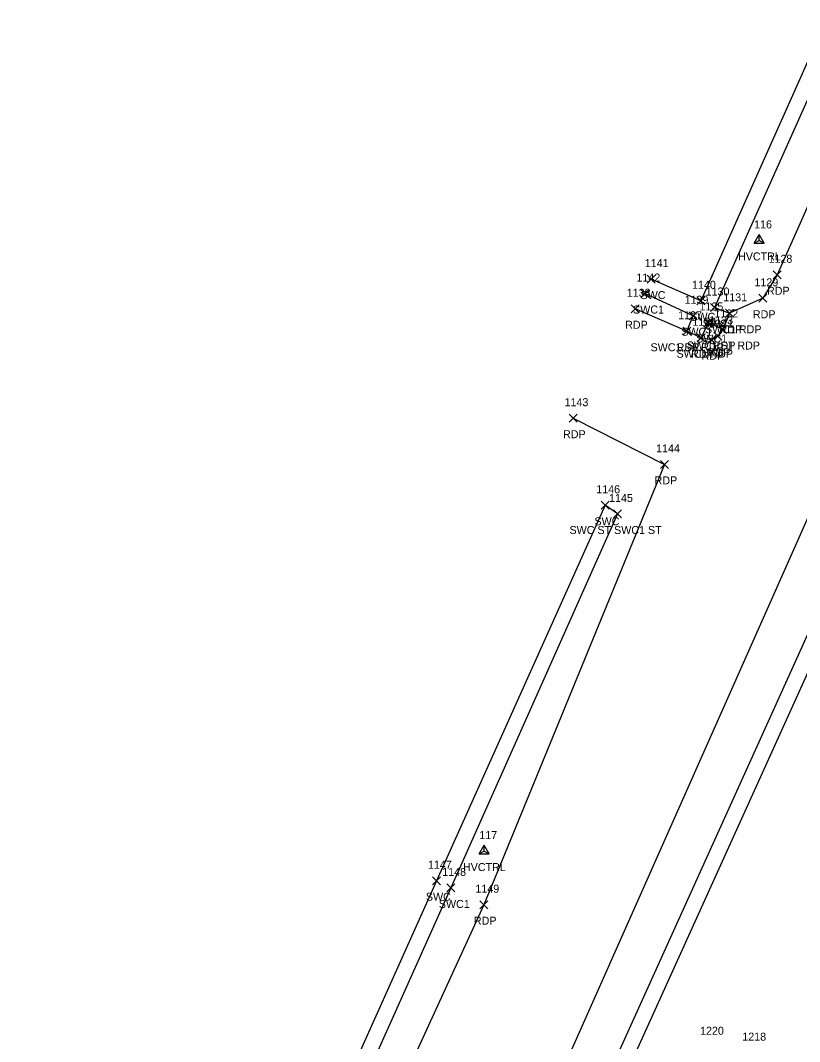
# Model space of a CAD drawing. Extents: x 1767353 to 1772625, y 740790 to 747702.
# Drawn here: x 1769882.6 to 1770077.3, y 742414.3 to 742669.5 of the extents above; entities that cross this region are included whole.
import ezdxf

# ---------------------------------------------------------------- set-up
doc = ezdxf.new("R2010")
doc.units = 0
for name, color, linetype in [('C_A', 7, 'Continuous'), ('C_I', 7, 'Continuous'), ('CPSM', 7, 'Continuous'), ('L_I', 7, 'Continuous'), ('P_A', 7, 'Continuous'), ('P_I', 7, 'Continuous'), ('P_TIC', 7, 'Continuous'), ('PET', 7, 'Continuous'), ('R_A', 7, 'Continuous'), ('R_I', 7, 'Continuous'), ('R_TIC', 7, 'Continuous'), ('RSW', 7, 'Continuous')]:
    doc.layers.add(name, color=color, linetype=linetype)

msp = doc.modelspace()

# ---------------------------------------------------------------- linework, layer by layer
at = {"layer": 'CPSM'}
for p, q in [((1770066.01, 742613.81), (1770067.26, 742615.97)), ((1770068.51, 742613.81), (1770067.26, 742615.97)), ((1770067.26, 742614.53), (1770067.26, 742615.97)), ((1770066.01, 742613.81), (1770067.26, 742614.53)), ((1770066.01, 742613.81), (1770068.51, 742613.81)), ((1770067.26, 742614.53), (1770067.26, 742614.53)), ((1770067.26, 742614.53), (1770068.51, 742613.81)), ((1769997.27, 742461.22), (1769998.52, 742463.38)), ((1769999.77, 742461.22), (1769998.52, 742463.38)), ((1769998.52, 742461.94), (1769998.52, 742463.38)), ((1769997.27, 742461.22), (1769998.52, 742461.94)), ((1769997.27, 742461.22), (1769999.77, 742461.22)), ((1769998.52, 742461.94), (1769998.52, 742461.94)), ((1769998.52, 742461.94), (1769999.77, 742461.22))]:
    msp.add_line(p, q, dxfattribs=at)
at = {"layer": 'P_TIC'}
for points in [[(1770070.7, 742604.94), (1770072.7, 742606.94)], [(1770072.7, 742604.94), (1770070.7, 742606.94)], [(1770067.18, 742599.07), (1770069.18, 742601.07)], [(1770069.18, 742599.07), (1770067.18, 742601.07)], [(1770035.26, 742596.45), (1770037.26, 742598.45)], [(1770037.26, 742596.45), (1770035.26, 742598.45)], [(1770058.84, 742595.32), (1770060.84, 742597.32)], [(1770060.84, 742595.32), (1770058.84, 742597.32)], [(1770048.12, 742590.83), (1770050.12, 742592.83)], [(1770050.12, 742590.83), (1770048.12, 742592.83)], [(1770057.18, 742591.27), (1770059.18, 742593.27)], [(1770059.18, 742591.27), (1770057.18, 742593.27)], [(1770051.72, 742589.21), (1770053.72, 742591.21)], [(1770053.72, 742589.21), (1770051.72, 742591.21)], [(1770054.34, 742588.72), (1770056.34, 742590.72)], [(1770056.34, 742588.72), (1770054.34, 742590.72)], [(1770055.9, 742589.58), (1770057.9, 742591.58)], [(1770057.9, 742589.58), (1770055.9, 742591.58)], [(1770019.73, 742569.11), (1770021.73, 742571.11)], [(1770021.73, 742569.11), (1770019.73, 742571.11)], [(1770042.61, 742557.57), (1770044.61, 742559.57)], [(1770044.61, 742557.57), (1770042.61, 742559.57)], [(1769997.45, 742447.54), (1769999.45, 742449.54)], [(1769999.45, 742447.54), (1769997.45, 742449.54)]]:
    msp.add_lwpolyline(points, dxfattribs=at)
at = {"layer": 'PET'}
for points in [[(1770287.36, 743218.01), (1770265.05, 743131.43), (1770236.51, 743031.56), (1770219.34, 742972.95), (1770201.78, 742917.74), (1770184.32, 742871.03), (1770170.89, 742832.33), (1770155.31, 742796.84), (1770127.15, 742730.43), (1770071.7, 742605.94), (1770068.18, 742600.07), (1770059.84, 742596.32), (1770058.18, 742592.27), (1770056.9, 742590.58), (1770055.34, 742589.72), (1770052.72, 742590.21), (1770049.12, 742591.83), (1770036.26, 742597.45)], [(1770147.48, 742699.94), (1770126.77, 742647.43), (1770093.35, 742575.6), (1770087.72, 742564.06), (1770014.02, 742398.02), (1769942.32, 742243.2), (1769914.15, 742124.85), (1769908.32, 742119.68), (1769902.88, 742101.36), (1769903.35, 742099.19), (1769904.66, 742097.46), (1769909.68, 742095.79), (1770083.39, 742045.68), (1770106.4, 742043.42), (1770086.96, 742009.25), (1770086.23, 742007.27), (1770086.55, 742005.47), (1770087.9, 742003.62), (1770089.26, 742002.56), (1770097.29, 741998.16), (1770140.08, 741981.73)], [(1770020.73, 742570.11), (1770043.61, 742558.57), (1769998.45, 742448.54), (1769947.65, 742337.89), (1769907.74, 742250.04), (1769890.69, 742225.86), (1769843.08, 742118.46), (1769841.73, 742116.98), (1769840.43, 742116.75), (1769837.14, 742117.6), (1769825.35, 742123.03), (1769532.9, 742252.54)]]:
    msp.add_lwpolyline(points, dxfattribs=at)
at = {"layer": 'R_TIC'}
for points in [[(1770039.21, 742603.87), (1770041.21, 742605.87)], [(1770041.21, 742603.87), (1770039.21, 742605.87)], [(1770037.69, 742600.26), (1770039.69, 742602.26)], [(1770039.69, 742600.26), (1770037.69, 742602.26)], [(1770051.67, 742598.45), (1770053.67, 742600.45)], [(1770053.67, 742598.45), (1770051.67, 742600.45)], [(1770055.07, 742596.76), (1770057.07, 742598.76)], [(1770057.07, 742596.76), (1770055.07, 742598.76)], [(1770049.74, 742594.71), (1770051.74, 742596.71)], [(1770051.74, 742594.71), (1770049.74, 742596.71)], [(1770058.84, 742595.32), (1770060.84, 742597.32)], [(1770060.84, 742595.32), (1770058.84, 742597.32)], [(1770048.12, 742590.83), (1770050.12, 742592.83)], [(1770050.12, 742590.83), (1770048.12, 742592.83)], [(1770053.46, 742593.02), (1770055.46, 742595.02)], [(1770055.46, 742593.02), (1770053.46, 742595.02)], [(1770057.18, 742591.27), (1770059.18, 742593.27)], [(1770059.18, 742591.27), (1770057.18, 742593.27)], [(1770051.72, 742589.21), (1770053.72, 742591.21)], [(1770053.72, 742589.21), (1770051.72, 742591.21)], [(1770027.71, 742547.34), (1770029.71, 742549.34)], [(1770029.71, 742547.34), (1770027.71, 742549.34)], [(1770030.85, 742545.17), (1770032.85, 742547.17)], [(1770032.85, 742545.17), (1770030.85, 742547.17)], [(1770030.85, 742545.17), (1770032.85, 742547.17)], [(1770032.85, 742545.17), (1770030.85, 742547.17)], [(1769985.57, 742453.53), (1769987.57, 742455.53)], [(1769987.57, 742453.53), (1769985.57, 742455.53)], [(1769989.14, 742451.72), (1769991.14, 742453.72)], [(1769991.14, 742451.72), (1769989.14, 742453.72)]]:
    msp.add_lwpolyline(points, dxfattribs=at)
at = {"layer": 'RSW'}
for points in [[(1770224.69, 743035.2), (1770205.97, 742977.24), (1770187.9, 742922.34), (1770172.36, 742876.56), (1770157.95, 742836.89), (1770142.69, 742800.86), (1770114.37, 742737.77), (1770052.67, 742599.45), (1770040.21, 742604.87)], [(1770228.29, 743034.19), (1770209.52, 742976.05), (1770191.6, 742920.92), (1770175.94, 742874.88), (1770161.68, 742835.7), (1770145.6, 742799.3), (1770117.99, 742736.11), (1770056.07, 742597.76), (1770059.84, 742596.32)], [(1770049.12, 742591.83), (1770050.74, 742595.71), (1770038.69, 742601.26)], [(1770058.18, 742592.27), (1770054.46, 742594.02), (1770052.72, 742590.21)], [(1770098.34, 742558.06), (1770024.1, 742393.92), (1769953.58, 742237.06), (1769937.36, 742200.11), (1769932.58, 742188.49)], [(1770098.34, 742558.06), (1770101.99, 742556.46), (1770027.61, 742392.19), (1769957.88, 742235.71), (1769937.16, 742186.55), (1769936.48, 742178.62)], [(1770031.85, 742546.17), (1770028.71, 742548.34), (1769986.57, 742454.53), (1769938.98, 742348.19), (1769898.43, 742257.44), (1769902.52, 742255.45)], [(1770031.85, 742546.17), (1769990.14, 742452.72), (1769941.49, 742344.14), (1769902.52, 742255.45)]]:
    msp.add_lwpolyline(points, dxfattribs=at)

# ---------------------------------------------------------------- texts
at = {"layer": 'C_A'}
for p in [(1770061.96, 742609.53), (1769993.21, 742456.94)]:
    msp.add_text('HVCTRL', height=2, dxfattribs=at).set_placement(p)
at = {"layer": 'C_I'}
for s, p in [('116', (1770065.98, 742617.53)), ('117', (1769997.29, 742464.94))]:
    msp.add_text(s, height=2, dxfattribs=at).set_placement(p)
at = {"layer": 'L_I'}
for s, p in [('1220', (1770052.47, 742416.04)), ('1218', (1770063.02, 742414.57))]:
    msp.add_text(s, height=2, dxfattribs=at).set_placement(p)
at = {"layer": 'P_A'}
for p in [(1770069.19, 742600.94), (1770065.67, 742595.07), (1770033.75, 742592.45), (1770057.33, 742591.32), (1770046.61, 742586.83), (1770054.39, 742585.58), (1770055.67, 742587.27), (1770050.21, 742585.21), (1770052.83, 742584.72), (1770018.21, 742565.11), (1770041.1, 742553.57), (1769995.94, 742443.54)]:
    msp.add_text('RDP', height=2, dxfattribs=at).set_placement(p)
at = {"layer": 'P_I'}
for s, p in [('1128', (1770069.57, 742608.94)), ('1129', (1770066.05, 742603.07)), ('1138', (1770034.14, 742600.45)), ('1131', (1770058.28, 742599.32)), ('1137', (1770046.99, 742594.83)), ('1136', (1770050.54, 742593.21)), ('1133', (1770054.77, 742593.58)), ('1132', (1770056.05, 742595.27)), ('1134', (1770053.21, 742592.72)), ('1143', (1770018.6, 742573.11)), ('1144', (1770041.48, 742561.57)), ('1149', (1769996.32, 742451.54))]:
    msp.add_text(s, height=2, dxfattribs=at).set_placement(p)
at = {"layer": 'R_A'}
for s, p in [('SWC', (1770037.57, 742599.87)), ('SWC1', (1770035.73, 742596.26)), ('SWC', (1770050.03, 742594.45)), ('SWC1', (1770047.78, 742590.71)), ('SWC1', (1770053.11, 742592.76)), ('SWC1 RDP', (1770053.7, 742591.32)), ('SWC1', (1770051.5, 742589.02)), ('SWC1 ST RDP', (1770040.09, 742586.83)), ('SWC1 ST RDP', (1770049.15, 742587.27)), ('SWC1 RDP', (1770046.59, 742585.21)), ('SWC', (1770026.07, 742543.34)), ('SWC ST SWC1 ST', (1770019.83, 742541.17)), ('SWC ST SWC1 ST', (1770019.83, 742541.17)), ('SWC', (1769983.94, 742449.53)), ('SWC1', (1769987.18, 742447.72))]:
    msp.add_text(s, height=2, dxfattribs=at).set_placement(p)
at = {"layer": 'R_I'}
for s, p in [('1141', (1770038.65, 742607.87)), ('1142', (1770036.56, 742604.26)), ('1140', (1770050.46, 742602.45)), ('1130', (1770053.86, 742600.76)), ('1139', (1770048.6, 742598.71)), ('1131', (1770058.28, 742599.32)), ('1135', (1770052.33, 742597.02)), ('1137', (1770046.99, 742594.83)), ('1136', (1770050.54, 742593.21)), ('1132', (1770056.05, 742595.27)), ('1146', (1770026.53, 742551.34)), ('1145', (1770029.73, 742549.17)), ('1145', (1770029.73, 742549.17)), ('1147', (1769984.45, 742457.53)), ('1148', (1769988.02, 742455.72))]:
    msp.add_text(s, height=2, dxfattribs=at).set_placement(p)

doc.saveas('drawing.dxf')
